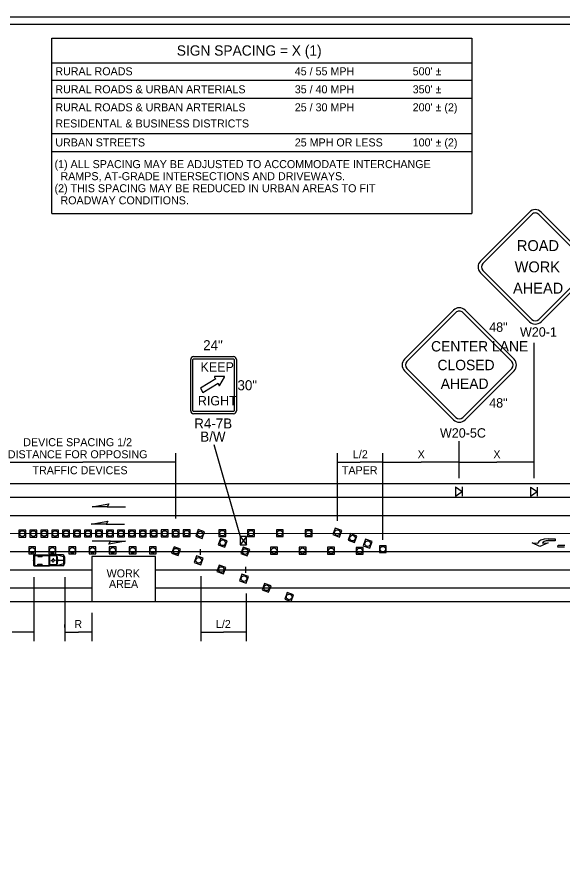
# Model space of a CAD drawing. Extents: x 99988 to 100172, y 99995 to 100047.
# Drawn here: x 100005.53 to 100010.31, y 100002.93 to 100010.44 of the extents above; entities that cross this region are included whole.
import ezdxf

# ---------------------------------------------------------------- set-up
doc = ezdxf.new("R2010")
doc.units = 0
for name, color, linetype in [('Default', 7, 'Continuous'), ('Level 15', 7, 'Continuous'), ('Level 20', 7, 'Continuous'), ('RD_MK_TrafficArrowType2LNew', 7, 'Continuous'), ('SH_DE_DetailBody1Text', 7, 'Continuous'), ('SH_GI_PlotLimits', 7, 'Continuous'), ('SH_GI_SheetBorder', 7, 'Continuous'), ('SH_GI_TrafficMvmntArrowRt1Lane', 7, 'Continuous'), ('SH_TI_BufferDataNote', 7, 'Continuous'), ('SH_TI_SignSpacing35to70Note', 7, 'Continuous'), ('TR_SN_RegulatorySigns', 7, 'Continuous'), ('TR_SN_WarningSigns', 7, 'Continuous'), ('TR_WZ_TrafficSafetyCone', 7, 'Continuous'), ('TR_WZ_TruckBuffer', 7, 'Continuous'), ('TR_WZ_WorkZoneDetails', 7, 'Continuous')]:
    doc.layers.add(name, color=color, linetype=linetype)

msp = doc.modelspace()

# ---------------------------------------------------------------- linework, layer by layer
at = {"layer": 'Default'}
for p, q in [((100009.3683, 100006.3287), (100009.426, 100006.2886)), ((100009.3683, 100006.3287), (100009.3683, 100006.2483)), ((100009.3683, 100006.2483), (100009.426, 100006.2886)), ((100009.426, 100006.3287), (100009.426, 100006.2483)), ((100010.0243, 100006.3277), (100010.0821, 100006.2876)), ((100010.0243, 100006.3277), (100010.0243, 100006.2473)), ((100010.0243, 100006.2473), (100010.0821, 100006.2876)), ((100010.0821, 100006.3277), (100010.0821, 100006.2473)), ((100000.2851, 100006.0802), (100006.7403, 100006.0802)), ((100010.7948, 100005.918), (100000.3647, 100005.9267)), ((100007.538, 100005.8939), (100007.4836, 100005.8213)), ((100007.4836, 100005.8939), (100007.538, 100005.8213)), ((100007.5108, 100005.8576), (100007.5108, 100005.8576)), ((100007.5109, 100005.8577), (100007.5109, 100005.8577)), ((100000.2916, 100005.7634), (100010.9542, 100005.7634)), ((100000.2873, 100005.6051), (100006.1821, 100005.6051))]:
    msp.add_line(p, q, dxfattribs=at)
msp.add_lwpolyline([(100007.538, 100005.8939), (100007.4836, 100005.8939), (100007.4836, 100005.8213), (100007.538, 100005.8213)], close=True, dxfattribs=at)
at = {"layer": 'Level 15'}
for p, q in [((100005.295, 100006.5446), (100006.1066, 100006.5446)), ((100006.9183, 100006.5446), (100006.1066, 100006.5446)), ((100008.3328, 100006.5446), (100008.5318, 100006.5446)), ((100008.7308, 100006.5446), (100008.5318, 100006.5446)), ((100008.7308, 100006.5446), (100009.0653, 100006.5446)), ((100009.3998, 100006.5446), (100009.0653, 100006.5446)), ((100009.3998, 100006.5446), (100009.7279, 100006.5446)), ((100010.056, 100006.5446), (100009.7279, 100006.5446)), ((100005.6757, 100005.0597), (100005.4876, 100005.0597)), ((100005.9477, 100005.0597), (100006.0662, 100005.0597)), ((100006.1848, 100005.0597), (100006.0662, 100005.0597)), ((100007.1369, 100005.0597), (100007.337, 100005.0597)), ((100007.537, 100005.0597), (100007.337, 100005.0597))]:
    msp.add_line(p, q, dxfattribs=at)
at = {"layer": 'RD_MK_TrafficArrowType2LNew'}
for p, q in [((100010.0877, 100005.8368), (100010.0877, 100005.8368)), ((100010.1293, 100005.8368), (100010.1293, 100005.8368)), ((100010.1793, 100005.8743), (100010.1793, 100005.8743)), ((100010.1793, 100005.8743), (100010.1793, 100005.8743)), ((100010.1793, 100005.8576), (100010.1793, 100005.8576))]:
    msp.add_line(p, q, dxfattribs=at)
for points in [[(100010.1293, 100005.8368), (100010.1793, 100005.8409), (100010.1043, 100005.8076), (100010.0377, 100005.8409), (100010.0877, 100005.8368)], [(100010.1793, 100005.8743), (100010.2377, 100005.8743), (100010.2377, 100005.8576), (100010.1793, 100005.8576)], [(100010.3222, 100005.8014), (100010.2638, 100005.802), (100010.264, 100005.8187), (100010.3224, 100005.8181)]]:
    msp.add_lwpolyline(points, dxfattribs=at)
for major_axis, ratio, start_param in [((-0.0917, 0), 0.40879, 4.712524), ((-0.05, 0), 0.41611, 4.712518)]:
    msp.add_ellipse((100010.1793, 100005.8368), major_axis=major_axis, ratio=ratio, start_param=start_param, end_param=6.283185, dxfattribs=at)
at = {"layer": 'SH_GI_PlotLimits'}
msp.add_lwpolyline([(99999.3125, 99999.9375), (100015.8125, 99999.9375), (100015.8125, 100010.4375), (99999.3125, 100010.4375)], close=True, dxfattribs=at)
at = {"layer": 'SH_GI_SheetBorder'}
msp.add_line((100000, 100010.375), (100015.75, 100010.375), dxfattribs=at)
msp.add_line((100000, 100010.375), (100015.75, 100010.375), dxfattribs=at)
at = {"layer": 'SH_GI_TrafficMvmntArrowRt1Lane'}
for p, q in [((100006.3183, 100006.1552), (100006.4791, 100006.1552)), ((100006.3084, 100006.0036), (100006.4691, 100006.0036)), ((100006.3467, 100005.8552), (100006.1859, 100005.8552))]:
    msp.add_line(p, q, dxfattribs=at)
for points in [[(100006.1873, 100006.1552), (100006.3332, 100006.1809), (100006.3183, 100006.1552)], [(100006.1774, 100006.0036), (100006.3233, 100006.0293), (100006.3084, 100006.0036)], [(100006.4777, 100005.8552), (100006.3318, 100005.8295), (100006.3467, 100005.8552)]]:
    msp.add_lwpolyline(points, close=True, dxfattribs=at)
at = {"layer": 'SH_TI_BufferDataNote'}
msp.add_line((100005.8337, 100008.7196), (100009.5092, 100008.7196), dxfattribs=at)
for points in [[(100005.8337, 100010.0386), (100005.8337, 100010.2532), (100009.5092, 100010.2532), (100009.5092, 100010.0386)], [(100005.8337, 100008.7196), (100005.8337, 100010.0386)], [(100009.5092, 100010.0484), (100009.5092, 100008.7196)]]:
    msp.add_lwpolyline(points, dxfattribs=at)
at = {"layer": 'SH_TI_SignSpacing35to70Note'}
for p, q in [((100005.8337, 100010.0386), (100009.5092, 100010.0386)), ((100005.8337, 100009.8854), (100009.5092, 100009.8854)), ((100005.8337, 100009.728), (100009.5092, 100009.728)), ((100005.8337, 100009.4206), (100009.5092, 100009.4206)), ((100005.8337, 100009.2632), (100009.5092, 100009.2632))]:
    msp.add_line(p, q, dxfattribs=at)
at = {"layer": 'TR_SN_RegulatorySigns'}
for p, q in [((100007.0745, 100007.4685), (100007.4246, 100007.4685)), ((100007.0495, 100006.9945), (100007.0495, 100007.4425)), ((100007.0692, 100006.9945), (100007.0692, 100007.4425)), ((100007.0745, 100007.448), (100007.4246, 100007.448)), ((100007.4299, 100007.4425), (100007.4299, 100006.9945)), ((100007.4495, 100007.4425), (100007.4495, 100006.9945)), ((100007.2705, 100007.273), (100007.1345, 100007.1912)), ((100007.1547, 100007.1549), (100007.2906, 100007.2367)), ((100007.2583, 100007.2864), (100007.2705, 100007.273)), ((100007.3416, 100007.2961), (100007.2615, 100007.2945)), ((100007.2906, 100007.2367), (100007.2956, 100007.2188)), ((100007.304, 100007.2177), (100007.3456, 100007.2888)), ((100007.1345, 100007.1912), (100007.1547, 100007.1549)), ((100007.4246, 100006.989), (100007.0745, 100006.989)), ((100007.4246, 100006.9685), (100007.0745, 100006.9685))]:
    msp.add_line(p, q, dxfattribs=at)
for centre, major_axis, ratio, start_param, end_param in [((100007.0745, 100007.4424), (0, -0.026), 0.960021, 3.141593, 4.712389), ((100007.4246, 100007.4424), (0, 0.026), 0.960021, 4.712389, 6.283185), ((100007.0745, 100007.4424), (0, -0.00555), 0.960051, 3.141593, 4.712389), ((100007.4246, 100007.4424), (0, 0.00555), 0.960051, 4.712389, 6.283185), ((100007.2616, 100007.2897), (0, 0.00478), 0.96, 0.019017, 2.328605), ((100007.3416, 100007.2913), (0, -0.00478), 0.96, 1.023619, 3.16061), ((100007.3, 100007.2202), (0, -0.00478), 0.96, 4.99813, 7.306805), ((100007.0745, 100006.9945), (0, -0.026), 0.960021, 4.712389, 6.283185), ((100007.0745, 100006.9945), (0, -0.00555), 0.960051, 4.712389, 6.283185), ((100007.4246, 100006.9945), (0, -0.00555), 0.960051, 0, 1.570796), ((100007.4246, 100006.9945), (0, -0.026), 0.960021, 0, 1.570796)]:
    msp.add_ellipse(centre, major_axis=major_axis, ratio=ratio, start_param=start_param, end_param=end_param, dxfattribs=at)
at = {"layer": 'TR_SN_WarningSigns'}
for p, q in [((100009.5854, 100008.3044), (100010.0138, 100008.7328)), ((100009.6058, 100008.284), (100010.0341, 100008.7124)), ((100010.0953, 100008.7124), (100010.5237, 100008.284)), ((100010.1157, 100008.7328), (100010.5441, 100008.3044)), ((100010.0341, 100007.7945), (100009.6058, 100008.2228)), ((100010.5237, 100008.2228), (100010.0953, 100007.7945)), ((100010.0137, 100007.7741), (100009.5854, 100008.2024)), ((100010.5441, 100008.2024), (100010.1157, 100007.7741)), ((100008.9205, 100007.4463), (100009.3488, 100007.8746)), ((100008.9409, 100007.4259), (100009.3692, 100007.8542)), ((100009.4304, 100007.8542), (100009.8588, 100007.4259)), ((100009.4508, 100007.8746), (100009.8791, 100007.4463)), ((100009.3488, 100006.916), (100008.9205, 100007.3443)), ((100009.3692, 100006.9364), (100008.9409, 100007.3647)), ((100009.8588, 100007.3647), (100009.4304, 100006.9364)), ((100009.8791, 100007.3443), (100009.4508, 100006.916))]:
    msp.add_line(p, q, dxfattribs=at)
for centre, radius, start, end in [((100010.0647, 100008.6818), 0.0721, 44.99628, 134.99965), ((100010.0647, 100008.6818), 0.0433, 44.99628, 134.99965), ((100009.6364, 100008.2534), 0.0721, 134.99658, 224.99358), ((100009.6364, 100008.2534), 0.0433, 134.99658, 224.99358), ((100009.3998, 100007.8236), 0.0721, 44.99628, 134.99965), ((100009.3998, 100007.8236), 0.0433, 44.99628, 134.99965), ((100010.0647, 100007.8251), 0.0721, 225, 314.99958), ((100010.0647, 100007.8251), 0.0433, 225, 314.99958), ((100008.9715, 100007.3953), 0.0721, 134.99658, 224.99358), ((100008.9715, 100007.3953), 0.0433, 134.99658, 224.99358), ((100009.8282, 100007.3953), 0.0433, 314.99936, 44.99485), ((100009.8282, 100007.3953), 0.0721, 314.99936, 44.99485), ((100009.3998, 100006.967), 0.0433, 225, 314.99958), ((100009.3998, 100006.967), 0.0721, 225, 314.99958)]:
    msp.add_arc(centre, radius, start, end, dxfattribs=at)
at = {"layer": 'TR_WZ_TrafficSafetyCone'}
for points in [[(100006.9838, 100005.894), (100007.0445, 100005.894), (100007.0445, 100005.9547), (100006.9838, 100005.9547)], [(100007.171, 100005.9352), (100007.1139, 100005.9559), (100007.0931, 100005.8989), (100007.1502, 100005.8781)], [(100007.2957, 100005.894), (100007.3564, 100005.894), (100007.3564, 100005.9548), (100007.2957, 100005.9548)], [(100007.5474, 100005.894), (100007.6081, 100005.894), (100007.6081, 100005.9548), (100007.5474, 100005.9548)], [(100007.7991, 100005.894), (100007.8598, 100005.894), (100007.8598, 100005.9548), (100007.7991, 100005.9548)], [(100008.0508, 100005.894), (100008.1116, 100005.894), (100008.1116, 100005.9548), (100008.0508, 100005.9548)], [(100008.2939, 100005.9113), (100008.351, 100005.8905), (100008.3717, 100005.9476), (100008.3147, 100005.9684)], [(100005.5454, 100005.8907), (100005.6061, 100005.8907), (100005.6061, 100005.9514), (100005.5454, 100005.9514)], [(100005.6413, 100005.8907), (100005.702, 100005.8907), (100005.702, 100005.9515), (100005.6413, 100005.9515)], [(100005.7372, 100005.8908), (100005.7979, 100005.8908), (100005.7979, 100005.9515), (100005.7372, 100005.9515)], [(100005.8331, 100005.8908), (100005.8938, 100005.8908), (100005.8938, 100005.9516), (100005.8331, 100005.9516)], [(100005.929, 100005.8909), (100005.9897, 100005.8909), (100005.9897, 100005.9516), (100005.929, 100005.9516)], [(100006.0249, 100005.8909), (100006.0856, 100005.8909), (100006.0856, 100005.9517), (100006.0249, 100005.9517)], [(100006.1208, 100005.891), (100006.1815, 100005.891), (100006.1815, 100005.9517), (100006.1208, 100005.9517)], [(100006.2167, 100005.891), (100006.2774, 100005.891), (100006.2774, 100005.9518), (100006.2167, 100005.9518)], [(100006.3126, 100005.8911), (100006.3733, 100005.8911), (100006.3733, 100005.9518), (100006.3126, 100005.9518)], [(100006.4085, 100005.8911), (100006.4692, 100005.8911), (100006.4692, 100005.9519), (100006.4085, 100005.9519)], [(100006.5044, 100005.8912), (100006.5651, 100005.8912), (100006.5651, 100005.9519), (100006.5044, 100005.9519)], [(100006.6003, 100005.8912), (100006.661, 100005.8912), (100006.661, 100005.952), (100006.6003, 100005.952)], [(100006.6962, 100005.8913), (100006.7569, 100005.8913), (100006.7569, 100005.952), (100006.6962, 100005.952)], [(100006.7921, 100005.8913), (100006.8528, 100005.8913), (100006.8528, 100005.9521), (100006.7921, 100005.9521)], [(100006.888, 100005.8914), (100006.9487, 100005.8914), (100006.9487, 100005.9521), (100006.888, 100005.9521)], [(100008.4265, 100005.863), (100008.4836, 100005.8422), (100008.5044, 100005.8993), (100008.4473, 100005.9201)], [(100005.6315, 100005.7438), (100005.6922, 100005.7438), (100005.6922, 100005.8045), (100005.6315, 100005.8045)], [(100005.8075, 100005.7438), (100005.8682, 100005.7438), (100005.8682, 100005.8045), (100005.8075, 100005.8045)], [(100005.9835, 100005.7438), (100006.0443, 100005.7438), (100006.0443, 100005.8045), (100005.9835, 100005.8045)], [(100006.1596, 100005.7438), (100006.2203, 100005.7438), (100006.2203, 100005.8045), (100006.1596, 100005.8045)], [(100006.3356, 100005.7438), (100006.3964, 100005.7438), (100006.3964, 100005.8045), (100006.3356, 100005.8045)], [(100006.5117, 100005.7438), (100006.5724, 100005.7438), (100006.5724, 100005.8045), (100006.5117, 100005.8045)], [(100006.6877, 100005.7438), (100006.7484, 100005.7438), (100006.7484, 100005.8045), (100006.6877, 100005.8045)], [(100006.8826, 100005.7487), (100006.9397, 100005.7279), (100006.9605, 100005.785), (100006.9034, 100005.8058)], [(100007.3683, 100005.8585), (100007.3112, 100005.8792), (100007.2905, 100005.8222), (100007.3475, 100005.8014)], [(100008.5592, 100005.8147), (100008.6163, 100005.794), (100008.637, 100005.851), (100008.58, 100005.8718)], [(100008.7004, 100005.7542), (100008.7611, 100005.7542), (100008.7611, 100005.815), (100008.7004, 100005.815)], [(100007.5657, 100005.7817), (100007.5086, 100005.8025), (100007.4878, 100005.7454), (100007.5449, 100005.7247)], [(100007.7477, 100005.7405), (100007.8085, 100005.7405), (100007.8085, 100005.8012), (100007.7477, 100005.8012)], [(100007.9979, 100005.7401), (100008.0586, 100005.7401), (100008.0586, 100005.8009), (100007.9979, 100005.8009)], [(100008.248, 100005.7398), (100008.3087, 100005.7398), (100008.3087, 100005.8005), (100008.248, 100005.8005)], [(100008.4981, 100005.7395), (100008.5588, 100005.7395), (100008.5588, 100005.8002), (100008.4981, 100005.8002)], [(100007.0806, 100005.6687), (100007.1377, 100005.6479), (100007.1585, 100005.705), (100007.1014, 100005.7257)], [(100007.2786, 100005.5886), (100007.3357, 100005.5679), (100007.3564, 100005.6249), (100007.2994, 100005.6457)], [(100007.4766, 100005.5086), (100007.5337, 100005.4878), (100007.5544, 100005.5449), (100007.4974, 100005.5657)], [(100007.6746, 100005.4286), (100007.7316, 100005.4078), (100007.7524, 100005.4649), (100007.6953, 100005.4856)], [(100007.8726, 100005.3485), (100007.9296, 100005.3278), (100007.9504, 100005.3848), (100007.8933, 100005.4056)]]:
    msp.add_lwpolyline(points, close=True, dxfattribs=at)
for centre in [(100005.5758, 100005.9211), (100005.6717, 100005.9211), (100005.7676, 100005.9212), (100005.8635, 100005.9212), (100005.9594, 100005.9213), (100006.0553, 100005.9213), (100006.1512, 100005.9214), (100006.2471, 100005.9214), (100006.343, 100005.9215), (100006.4389, 100005.9215), (100006.5348, 100005.9216), (100006.6306, 100005.9216), (100006.7265, 100005.9217), (100006.8224, 100005.9217), (100006.9183, 100005.9218), (100007.0142, 100005.9243), (100007.132, 100005.917), (100007.326, 100005.9244), (100007.5778, 100005.9244), (100007.8295, 100005.9244), (100008.0812, 100005.9244), (100008.3328, 100005.9294), (100008.4655, 100005.8812), (100007.3294, 100005.8403), (100008.5981, 100005.8329), (100008.7308, 100005.7846), (100005.6618, 100005.7741), (100005.8379, 100005.7741), (100006.0139, 100005.7741), (100006.1899, 100005.7741), (100006.366, 100005.7741), (100006.542, 100005.7741), (100006.7181, 100005.7741), (100006.9215, 100005.7669), (100007.5267, 100005.7636), (100007.7781, 100005.7708), (100008.0282, 100005.7705), (100008.2783, 100005.7702), (100008.5284, 100005.7698), (100007.1195, 100005.6868), (100007.3175, 100005.6068), (100007.5155, 100005.5267), (100007.7135, 100005.4467), (100007.9115, 100005.3667)]:
    msp.add_circle(centre, 0.0244, dxfattribs=at)
at = {"layer": 'TR_WZ_TruckBuffer'}
for p, q in [((100005.6724, 100005.7298), (100005.6724, 100005.6434)), ((100005.6753, 100005.7327), (100005.6782, 100005.7327)), ((100005.6782, 100005.7327), (100005.6782, 100005.6405)), ((100005.6787, 100005.7343), (100005.8127, 100005.7343)), ((100005.6787, 100005.7343), (100005.6787, 100005.639)), ((100005.6825, 100005.7305), (100005.6825, 100005.6428)), ((100005.6825, 100005.7305), (100005.8089, 100005.7305)), ((100005.7127, 100005.7305), (100005.7127, 100005.7195)), ((100005.7198, 100005.7305), (100005.7198, 100005.7195)), ((100005.742, 100005.7305), (100005.742, 100005.7195)), ((100005.7485, 100005.7305), (100005.7485, 100005.7195)), ((100005.8089, 100005.7305), (100005.8089, 100005.6428)), ((100005.8127, 100005.7343), (100005.8127, 100005.639)), ((100005.8145, 100005.7343), (100005.8145, 100005.639)), ((100005.9375, 100005.7343), (100005.8145, 100005.7343)), ((100005.8313, 100005.7356), (100005.8239, 100005.7356)), ((100005.8749, 100005.7343), (100005.8671, 100005.7269)), ((100005.8749, 100005.7343), (100005.8749, 100005.639)), ((100005.876, 100005.7343), (100005.876, 100005.639)), ((100005.9375, 100005.7168), (100005.876, 100005.7343)), ((100005.9375, 100005.7343), (100005.9375, 100005.639)), ((100005.9375, 100005.7343), (100005.9436, 100005.715)), ((100005.6724, 100005.6933), (100005.6782, 100005.6915)), ((100005.6724, 100005.6799), (100005.6782, 100005.6817)), ((100005.674, 100005.6866), (100005.6767, 100005.6866)), ((100005.6753, 100005.688), (100005.6753, 100005.6853)), ((100005.7127, 100005.7195), (100005.7485, 100005.7195)), ((100005.8749, 100005.7269), (100005.8145, 100005.7269)), ((100005.8253, 100005.6863), (100005.8349, 100005.6864)), ((100005.8362, 100005.6865), (100005.8362, 100005.6865)), ((100005.8449, 100005.6683), (100005.8451, 100005.6755)), ((100005.8454, 100005.7055), (100005.8454, 100005.6978)), ((100005.865, 100005.6867), (100005.8568, 100005.6867)), ((100005.9375, 100005.6564), (100005.876, 100005.639)), ((100005.9375, 100005.6866), (100005.8881, 100005.6866)), ((100005.9375, 100005.639), (100005.9436, 100005.6582)), ((100005.9436, 100005.715), (100005.9436, 100005.6582)), ((100005.6753, 100005.6405), (100005.6782, 100005.6405)), ((100005.6787, 100005.639), (100005.8127, 100005.639)), ((100005.6825, 100005.6428), (100005.8089, 100005.6428)), ((100005.7127, 100005.6428), (100005.7127, 100005.6537)), ((100005.7127, 100005.6537), (100005.7485, 100005.6537)), ((100005.7198, 100005.6428), (100005.7198, 100005.6537)), ((100005.742, 100005.6428), (100005.742, 100005.6537)), ((100005.7485, 100005.6428), (100005.7485, 100005.6537)), ((100005.8749, 100005.6464), (100005.8145, 100005.6464)), ((100005.9375, 100005.639), (100005.8145, 100005.639)), ((100005.8313, 100005.6376), (100005.8239, 100005.6376)), ((100005.8684, 100005.6464), (100005.8749, 100005.639))]:
    msp.add_line(p, q, dxfattribs=at)
for centre, radius in [((100005.6753, 100005.6866), 0.00134), ((100005.8454, 100005.6866), 0.00918)]:
    msp.add_circle(centre, radius, dxfattribs=at)
for centre, radius, start, end in [((100005.6753, 100005.7298), 0.00291, 90, 179.99999), ((100005.7881, 100005.6866), 0.1, 331.55054, 28.46005), ((100005.6753, 100005.6434), 0.00291, 180, 270)]:
    msp.add_arc(centre, radius, start, end, dxfattribs=at)
at = {"layer": 'TR_WZ_WorkZoneDetails'}
for p, q in [((100010.056, 100006.4068), (100010.056, 100007.5897)), ((100009.3998, 100006.4068), (100009.3998, 100006.7282)), ((100007.2519, 100006.6985), (100007.4836, 100005.8939)), ((100006.9183, 100006.0521), (100006.9183, 100006.6246)), ((100008.3328, 100006.031), (100008.3328, 100006.6246)), ((100008.7308, 100005.8668), (100008.7308, 100006.6246)), ((100000.2873, 100006.3578), (100006.7403, 100006.3578)), ((100006.7403, 100006.3578), (100010.4004, 100006.3578)), ((100000.2873, 100006.2386), (100006.7403, 100006.2386)), ((100006.7403, 100006.2386), (100010.9576, 100006.2386)), ((100006.7403, 100006.0802), (100010.9576, 100006.0802)), ((100007.132, 100005.7847), (100007.132, 100005.7337)), ((100006.7403, 100005.6051), (100010.9446, 100005.6051)), ((100007.5322, 100005.5777), (100007.5322, 100005.6293)), ((100005.6757, 100005.539), (100005.6757, 100004.9797)), ((100005.9477, 100005.539), (100005.9477, 100004.9797)), ((100007.1369, 100005.5482), (100007.1369, 100004.9797)), ((100003.3501, 100005.4467), (100006.1821, 100005.4467)), ((100006.7403, 100005.4467), (100010.9576, 100005.4467)), ((100007.537, 100004.9797), (100007.537, 100005.3971)), ((100000.8604, 100005.3275), (100006.7403, 100005.3275)), ((100006.7403, 100005.3275), (100010.9576, 100005.3275)), ((100006.1848, 100005.2277), (100006.1848, 100004.9797)), ((100005.9477, 100005.0997), (100005.9477, 100005.1242))]:
    msp.add_line(p, q, dxfattribs=at)
msp.add_lwpolyline([(100006.185, 100005.3277), (100006.7403, 100005.3277), (100006.7403, 100005.7215), (100006.185, 100005.7215)], close=True, dxfattribs=at)

# ---------------------------------------------------------------- texts
at = {"layer": 'Level 20'}
for s, p in [('DEVICE SPACING 1/2', (100005.5843, 100006.6851)), ('DISTANCE FOR OPPOSING', (100005.449, 100006.5796)), ('L/2', (100008.469, 100006.5796)), ('X', (100009.0356, 100006.5796)), ('TRAFFIC DEVICES', (100005.665, 100006.4396)), ('TAPER', (100008.3728, 100006.4396)), ('R', (100006.0312, 100005.0947))]:
    msp.add_text(s, height=0.07, dxfattribs=at).set_placement(p)
for s, p in [('X', (100009.6982, 100006.5796)), ('L/2', (100007.2703, 100005.0947))]:
    msp.add_text(s, height=0.07, rotation=360, dxfattribs=at).set_placement(p)
at = {"layer": 'SH_DE_DetailBody1Text'}
for s, p in [('WORK ', (100006.3137, 100005.5376)), ('AREA', (100006.3345, 100005.4451))]:
    msp.add_text(s, height=0.07, dxfattribs=at).set_placement(p)
at = {"layer": 'SH_TI_SignSpacing35to70Note'}
for s, height, p in [('SIGN SPACING = X (1)', 0.09, (100006.9278, 100010.1009)), ('RURAL ROADS', 0.07, (100005.8647, 100009.9291)), ('45 / 55 MPH', 0.07, (100007.9603, 100009.9291)), ("500' ±", 0.07, (100008.9923, 100009.9291)), ('RURAL ROADS & URBAN ARTERIALS', 0.07, (100005.8647, 100009.7717)), ('35 / 40 MPH', 0.07, (100007.9603, 100009.7717)), ("350' ± ", 0.07, (100008.9923, 100009.7717)), ('RURAL ROADS & URBAN ARTERIALS', 0.07, (100005.8647, 100009.614)), ('25 / 30 MPH', 0.07, (100007.9603, 100009.6143)), ("200' ± (2)", 0.07, (100008.9923, 100009.6143)), ('RESIDENTAL & BUSINESS DISTRICTS', 0.07, (100005.8647, 100009.4729)), ('URBAN STREETS', 0.07, (100005.8647, 100009.3069)), ('25 MPH OR LESS', 0.07, (100007.9603, 100009.3069)), ("100' ± (2) ", 0.07, (100008.9923, 100009.3069)), ('(1) ALL SPACING MAY BE ADJUSTED TO ACCOMMODATE INTERCHANGE ', 0.07, (100005.8578, 100009.1173)), ('  RAMPS, AT-GRADE INTERSECTIONS AND DRIVEWAYS.', 0.07, (100005.8578, 100009.0118)), ('(2) THIS SPACING MAY BE REDUCED IN URBAN AREAS TO FIT  ', 0.07, (100005.8578, 100008.9062)), ('  ROADWAY CONDITIONS.', 0.07, (100005.8578, 100008.8006))]:
    msp.add_text(s, height=height, dxfattribs=at).set_placement(p)
at = {"layer": 'TR_SN_RegulatorySigns'}
for s, height, p in [('24"', 0.0875, (100007.1587, 100007.5247)), ('KEEP', 0.08197, (100007.1352, 100007.3371)), ('30"', 0.0875, (100007.4587, 100007.1747)), ('RIGHT', 0.08197, (100007.1118, 100007.0418)), ('R4-7B', 0.0875, (100007.0803, 100006.8404)), ('B/W', 0.0875, (100007.1332, 100006.7249))]:
    msp.add_text(s, height=height, dxfattribs=at).set_placement(p)
at = {"layer": 'TR_SN_WarningSigns'}
for s, height, p in [('ROAD', 0.0954, (100009.9042, 100008.392)), ('WORK', 0.0954, (100009.8846, 100008.2058)), ('AHEAD', 0.0954, (100009.8702, 100008.0195)), ('48"', 0.08203, (100009.6619, 100007.6857)), ('W20-1', 0.08203, (100009.9312, 100007.6434)), ('CENTER LANE', 0.090854, (100009.1531, 100007.5134)), ('CLOSED', 0.09085, (100009.2092, 100007.3499)), ('AHEAD', 0.09085, (100009.2377, 100007.1863)), ('48"', 0.08203, (100009.6619, 100007.0228)), ('W20-5C', 0.08203, (100009.2309, 100006.7601))]:
    msp.add_text(s, height=height, dxfattribs=at).set_placement(p)

doc.saveas('drawing.dxf')
